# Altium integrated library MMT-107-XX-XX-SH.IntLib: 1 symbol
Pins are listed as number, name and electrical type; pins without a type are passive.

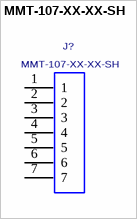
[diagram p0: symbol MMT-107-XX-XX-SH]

## MMT-107-XX-XX-SH
designator J?
2MM HORIZONTAL TERMINAL SURFACE MOUNT STRIP ASM.; MANUFACTURER: SAMTEC
footprint MMT-107-XX-XX-SH
pins: 1, 2, 3, 4, 5, 6, 7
